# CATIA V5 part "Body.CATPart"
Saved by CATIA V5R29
Part number: Body
Source: Unknown
Bounding box of the stored display mesh (mm): x -80 to 80, y -1.964 to 458.036, z -80 to 100
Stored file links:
  C:\가치같이\SmartFactory_BoxErectorConveyor\Boxing(over)\Body.CATPart
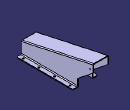
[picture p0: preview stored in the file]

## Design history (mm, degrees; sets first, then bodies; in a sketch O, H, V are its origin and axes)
Body1 (main body)
  Solid1 "PartBody": solid without history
